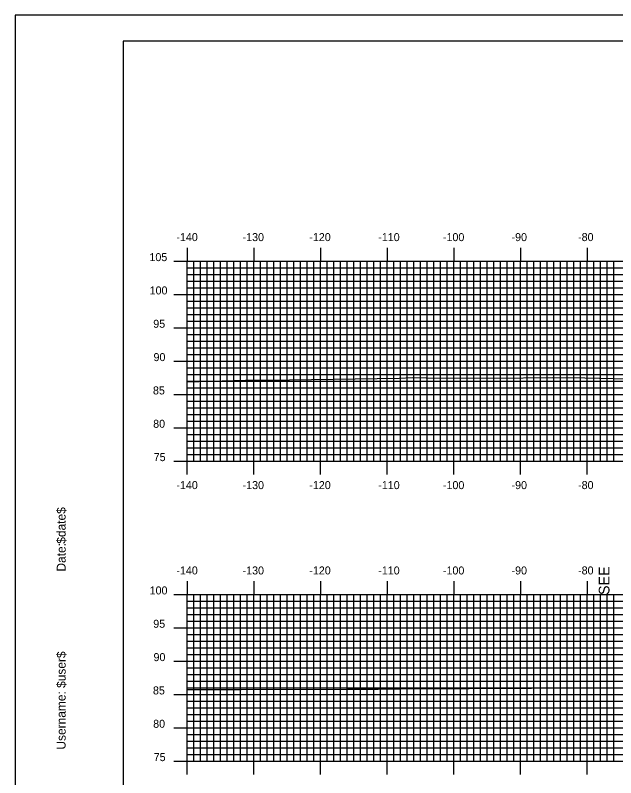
# Model space of a CAD drawing. Extents: x 854116 to 854460, y 364366 to 364586.
# Drawn here: x 854116.4 to 854206.5, y 364471.3 to 364585.7 of the extents above; entities that cross this region are included whole.
import ezdxf

# ---------------------------------------------------------------- set-up
doc = ezdxf.new("R2010")
doc.units = 0
for name, color, linetype in [('ANNOTATION', 7, 'Continuous'), ('BORDER', 7, 'Continuous'), ('H_V ANNOTATION', 7, 'Continuous'), ('MAJOR', 7, 'Continuous'), ('MINOR', 7, 'Continuous'), ('PLOT BOUNDARY', 7, 'Continuous'), ('S_Roadway_Centerline', 7, 'Continuous')]:
    doc.layers.add(name, color=color, linetype=linetype)

msp = doc.modelspace()

# ---------------------------------------------------------------- linework, layer by layer
at = {"layer": 'BORDER'}
msp.add_lwpolyline([(854132.63, 364371.79), (854452.63, 364371.79), (854452.63, 364581.79), (854132.63, 364581.79)], close=True, dxfattribs=at)
at = {"layer": 'MAJOR'}
for p, q in [((854142.23, 364550.79), (854142.23, 364548.79)), ((854152.23, 364550.79), (854152.23, 364548.79)), ((854162.23, 364550.79), (854162.23, 364548.79)), ((854172.23, 364550.79), (854172.23, 364548.79)), ((854182.23, 364550.79), (854182.23, 364548.79)), ((854192.23, 364550.79), (854192.23, 364548.79)), ((854202.23, 364550.79), (854202.23, 364548.79)), ((854140.23, 364548.79), (854142.23, 364548.79)), ((854142.23, 364548.79), (854422.23, 364548.79)), ((854142.23, 364518.79), (854142.23, 364548.79)), ((854142.23, 364518.79), (854142.23, 364548.79)), ((854142.23, 364548.79), (854422.23, 364548.79)), ((854152.23, 364518.79), (854152.23, 364548.79)), ((854162.23, 364518.79), (854162.23, 364548.79)), ((854172.23, 364518.79), (854172.23, 364548.79)), ((854182.23, 364518.79), (854182.23, 364548.79)), ((854192.23, 364518.79), (854192.23, 364548.79)), ((854202.23, 364518.79), (854202.23, 364548.79)), ((854140.23, 364543.79), (854142.23, 364543.79)), ((854142.23, 364543.79), (854422.23, 364543.79)), ((854140.23, 364538.79), (854142.23, 364538.79)), ((854142.23, 364538.79), (854422.23, 364538.79)), ((854140.23, 364533.79), (854142.23, 364533.79)), ((854142.23, 364533.79), (854422.23, 364533.79)), ((854140.23, 364528.79), (854142.23, 364528.79)), ((854142.23, 364528.79), (854422.23, 364528.79)), ((854140.23, 364523.79), (854142.23, 364523.79)), ((854142.23, 364523.79), (854422.23, 364523.79)), ((854140.23, 364518.79), (854142.23, 364518.79)), ((854142.23, 364518.79), (854422.23, 364518.79)), ((854142.23, 364518.79), (854422.23, 364518.79)), ((854142.23, 364516.78), (854142.23, 364518.79)), ((854152.23, 364516.78), (854152.23, 364518.79)), ((854162.23, 364516.78), (854162.23, 364518.79)), ((854172.23, 364516.78), (854172.23, 364518.79)), ((854182.23, 364516.78), (854182.23, 364518.79)), ((854192.23, 364516.78), (854192.23, 364518.79)), ((854202.23, 364516.78), (854202.23, 364518.79)), ((854142.23, 364500.79), (854142.23, 364498.79)), ((854152.23, 364500.79), (854152.23, 364498.79)), ((854162.23, 364500.79), (854162.23, 364498.79)), ((854172.23, 364500.79), (854172.23, 364498.79)), ((854182.23, 364500.79), (854182.23, 364498.79)), ((854192.23, 364500.79), (854192.23, 364498.79)), ((854202.23, 364500.79), (854202.23, 364498.79)), ((854140.23, 364498.79), (854142.23, 364498.79)), ((854142.23, 364498.79), (854422.23, 364498.79)), ((854142.23, 364473.79), (854142.23, 364498.79)), ((854142.23, 364473.79), (854142.23, 364498.79)), ((854142.23, 364498.79), (854422.23, 364498.79)), ((854152.23, 364473.79), (854152.23, 364498.79)), ((854162.23, 364473.79), (854162.23, 364498.79)), ((854172.23, 364473.79), (854172.23, 364498.79)), ((854182.23, 364473.79), (854182.23, 364498.79)), ((854192.23, 364473.79), (854192.23, 364498.79)), ((854202.23, 364473.79), (854202.23, 364498.79)), ((854140.23, 364493.79), (854142.23, 364493.79)), ((854142.23, 364493.79), (854422.23, 364493.79)), ((854140.23, 364488.79), (854142.23, 364488.79)), ((854142.23, 364488.79), (854422.23, 364488.79)), ((854140.23, 364483.79), (854142.23, 364483.79)), ((854142.23, 364483.79), (854422.23, 364483.79)), ((854140.23, 364478.79), (854142.23, 364478.79)), ((854142.23, 364478.79), (854422.23, 364478.79)), ((854140.23, 364473.79), (854142.23, 364473.79)), ((854142.23, 364473.79), (854422.23, 364473.79)), ((854142.23, 364473.79), (854422.23, 364473.79)), ((854142.23, 364471.78), (854142.23, 364473.79)), ((854152.23, 364471.78), (854152.23, 364473.79)), ((854162.23, 364471.78), (854162.23, 364473.79)), ((854172.23, 364471.78), (854172.23, 364473.79)), ((854182.23, 364471.78), (854182.23, 364473.79)), ((854192.23, 364471.78), (854192.23, 364473.79)), ((854202.23, 364471.78), (854202.23, 364473.79))]:
    msp.add_line(p, q, dxfattribs=at)
at = {"layer": 'MINOR'}
for p, q in [((854143.23, 364518.79), (854143.23, 364548.79)), ((854144.23, 364518.79), (854144.23, 364548.79)), ((854145.23, 364518.79), (854145.23, 364548.79)), ((854146.23, 364518.79), (854146.23, 364548.79)), ((854147.23, 364518.79), (854147.23, 364548.79)), ((854148.23, 364518.79), (854148.23, 364548.79)), ((854149.23, 364518.79), (854149.23, 364548.79)), ((854150.23, 364518.79), (854150.23, 364548.79)), ((854151.23, 364518.79), (854151.23, 364548.79)), ((854153.23, 364518.79), (854153.23, 364548.79)), ((854154.23, 364518.79), (854154.23, 364548.79)), ((854155.23, 364518.79), (854155.23, 364548.79)), ((854156.23, 364518.79), (854156.23, 364548.79)), ((854157.23, 364518.79), (854157.23, 364548.79)), ((854158.23, 364518.79), (854158.23, 364548.79)), ((854159.23, 364518.79), (854159.23, 364548.79)), ((854160.23, 364518.79), (854160.23, 364548.79)), ((854161.23, 364518.79), (854161.23, 364548.79)), ((854163.23, 364518.79), (854163.23, 364548.79)), ((854164.23, 364518.79), (854164.23, 364548.79)), ((854165.23, 364518.79), (854165.23, 364548.79)), ((854166.23, 364518.79), (854166.23, 364548.79)), ((854167.23, 364518.79), (854167.23, 364548.79)), ((854168.23, 364518.79), (854168.23, 364548.79)), ((854169.23, 364518.79), (854169.23, 364548.79)), ((854170.23, 364518.79), (854170.23, 364548.79)), ((854171.23, 364518.79), (854171.23, 364548.79)), ((854173.23, 364518.79), (854173.23, 364548.79)), ((854174.23, 364518.79), (854174.23, 364548.79)), ((854175.23, 364518.79), (854175.23, 364548.79)), ((854176.23, 364518.79), (854176.23, 364548.79)), ((854177.23, 364518.79), (854177.23, 364548.79)), ((854178.23, 364518.79), (854178.23, 364548.79)), ((854179.23, 364518.79), (854179.23, 364548.79)), ((854180.23, 364518.79), (854180.23, 364548.79)), ((854181.23, 364518.79), (854181.23, 364548.79)), ((854183.23, 364518.79), (854183.23, 364548.79)), ((854184.23, 364518.79), (854184.23, 364548.79)), ((854185.23, 364518.79), (854185.23, 364548.79)), ((854186.23, 364518.79), (854186.23, 364548.79)), ((854187.23, 364518.79), (854187.23, 364548.79)), ((854188.23, 364518.79), (854188.23, 364548.79)), ((854189.23, 364518.79), (854189.23, 364548.79)), ((854190.23, 364518.79), (854190.23, 364548.79)), ((854191.23, 364518.79), (854191.23, 364548.79)), ((854193.23, 364518.79), (854193.23, 364548.79)), ((854194.23, 364518.79), (854194.23, 364548.79)), ((854195.23, 364518.79), (854195.23, 364548.79)), ((854196.23, 364518.79), (854196.23, 364548.79)), ((854197.23, 364518.79), (854197.23, 364548.79)), ((854198.23, 364518.79), (854198.23, 364548.79)), ((854199.23, 364518.79), (854199.23, 364548.79)), ((854200.23, 364518.79), (854200.23, 364548.79)), ((854201.23, 364518.79), (854201.23, 364548.79)), ((854203.23, 364518.79), (854203.23, 364548.79)), ((854204.23, 364518.79), (854204.23, 364548.79)), ((854205.23, 364518.79), (854205.23, 364548.79)), ((854206.23, 364518.79), (854206.23, 364548.79)), ((854142.23, 364547.79), (854422.23, 364547.79)), ((854142.23, 364547.79), (854144.23, 364547.79)), ((854142.23, 364546.79), (854422.23, 364546.79)), ((854142.23, 364546.79), (854144.23, 364546.79)), ((854142.23, 364545.79), (854422.23, 364545.79)), ((854142.23, 364545.79), (854144.23, 364545.79)), ((854142.23, 364544.79), (854422.23, 364544.79)), ((854142.23, 364544.79), (854144.23, 364544.79)), ((854142.23, 364542.79), (854422.23, 364542.79)), ((854142.23, 364542.79), (854144.23, 364542.79)), ((854142.23, 364541.79), (854422.23, 364541.79)), ((854142.23, 364541.79), (854144.23, 364541.79)), ((854142.23, 364540.79), (854422.23, 364540.79)), ((854142.23, 364540.79), (854144.23, 364540.79)), ((854142.23, 364539.79), (854422.23, 364539.79)), ((854142.23, 364539.79), (854144.23, 364539.79)), ((854142.23, 364537.79), (854422.23, 364537.79)), ((854142.23, 364537.79), (854144.23, 364537.79)), ((854142.23, 364536.79), (854422.23, 364536.79)), ((854142.23, 364536.79), (854144.23, 364536.79)), ((854142.23, 364535.79), (854422.23, 364535.79)), ((854142.23, 364535.79), (854144.23, 364535.79)), ((854142.23, 364534.79), (854422.23, 364534.79)), ((854142.23, 364534.79), (854144.23, 364534.79)), ((854142.23, 364532.79), (854422.23, 364532.79)), ((854142.23, 364532.79), (854144.23, 364532.79)), ((854142.23, 364531.79), (854422.23, 364531.79)), ((854142.23, 364531.79), (854144.23, 364531.79)), ((854142.23, 364530.79), (854422.23, 364530.79)), ((854142.23, 364530.79), (854144.23, 364530.79)), ((854142.23, 364529.79), (854422.23, 364529.79)), ((854142.23, 364529.79), (854144.23, 364529.79)), ((854142.23, 364527.79), (854422.23, 364527.79)), ((854142.23, 364527.79), (854144.23, 364527.79)), ((854142.23, 364526.79), (854422.23, 364526.79)), ((854142.23, 364526.79), (854144.23, 364526.79)), ((854142.23, 364525.79), (854422.23, 364525.79)), ((854142.23, 364525.79), (854144.23, 364525.79)), ((854142.23, 364524.79), (854422.23, 364524.79)), ((854142.23, 364524.79), (854144.23, 364524.79)), ((854142.23, 364522.79), (854422.23, 364522.79)), ((854142.23, 364522.79), (854144.23, 364522.79)), ((854142.23, 364521.79), (854422.23, 364521.79)), ((854142.23, 364521.79), (854144.23, 364521.79)), ((854142.23, 364520.79), (854422.23, 364520.79)), ((854142.23, 364520.79), (854144.23, 364520.79)), ((854142.23, 364519.79), (854422.23, 364519.79)), ((854142.23, 364519.79), (854144.23, 364519.79)), ((854143.23, 364473.79), (854143.23, 364498.79)), ((854144.23, 364473.79), (854144.23, 364498.79)), ((854145.23, 364473.79), (854145.23, 364498.79)), ((854146.23, 364473.79), (854146.23, 364498.79)), ((854147.23, 364473.79), (854147.23, 364498.79)), ((854148.23, 364473.79), (854148.23, 364498.79)), ((854149.23, 364473.79), (854149.23, 364498.79)), ((854150.23, 364473.79), (854150.23, 364498.79)), ((854151.23, 364473.79), (854151.23, 364498.79)), ((854153.23, 364473.79), (854153.23, 364498.79)), ((854154.23, 364473.79), (854154.23, 364498.79)), ((854155.23, 364473.79), (854155.23, 364498.79)), ((854156.23, 364473.79), (854156.23, 364498.79)), ((854157.23, 364473.79), (854157.23, 364498.79)), ((854158.23, 364473.79), (854158.23, 364498.79)), ((854159.23, 364473.79), (854159.23, 364498.79)), ((854160.23, 364473.79), (854160.23, 364498.79)), ((854161.23, 364473.79), (854161.23, 364498.79)), ((854163.23, 364473.79), (854163.23, 364498.79)), ((854164.23, 364473.79), (854164.23, 364498.79)), ((854165.23, 364473.79), (854165.23, 364498.79)), ((854166.23, 364473.79), (854166.23, 364498.79)), ((854167.23, 364473.79), (854167.23, 364498.79)), ((854168.23, 364473.79), (854168.23, 364498.79)), ((854169.23, 364473.79), (854169.23, 364498.79)), ((854170.23, 364473.79), (854170.23, 364498.79)), ((854171.23, 364473.79), (854171.23, 364498.79)), ((854173.23, 364473.79), (854173.23, 364498.79)), ((854174.23, 364473.79), (854174.23, 364498.79)), ((854175.23, 364473.79), (854175.23, 364498.79)), ((854176.23, 364473.79), (854176.23, 364498.79)), ((854177.23, 364473.79), (854177.23, 364498.79)), ((854178.23, 364473.79), (854178.23, 364498.79)), ((854179.23, 364473.79), (854179.23, 364498.79)), ((854180.23, 364473.79), (854180.23, 364498.79)), ((854181.23, 364473.79), (854181.23, 364498.79)), ((854183.23, 364473.79), (854183.23, 364498.79)), ((854184.23, 364473.79), (854184.23, 364498.79)), ((854185.23, 364473.79), (854185.23, 364498.79)), ((854186.23, 364473.79), (854186.23, 364498.79)), ((854187.23, 364473.79), (854187.23, 364498.79)), ((854188.23, 364473.79), (854188.23, 364498.79)), ((854189.23, 364473.79), (854189.23, 364498.79)), ((854190.23, 364473.79), (854190.23, 364498.79)), ((854191.23, 364473.79), (854191.23, 364498.79)), ((854193.23, 364473.79), (854193.23, 364498.79)), ((854194.23, 364473.79), (854194.23, 364498.79)), ((854195.23, 364473.79), (854195.23, 364498.79)), ((854196.23, 364473.79), (854196.23, 364498.79)), ((854197.23, 364473.79), (854197.23, 364498.79)), ((854198.23, 364473.79), (854198.23, 364498.79)), ((854199.23, 364473.79), (854199.23, 364498.79)), ((854200.23, 364473.79), (854200.23, 364498.79)), ((854201.23, 364473.79), (854201.23, 364498.79)), ((854203.23, 364473.79), (854203.23, 364498.79)), ((854204.23, 364473.79), (854204.23, 364498.79)), ((854205.23, 364473.79), (854205.23, 364498.79)), ((854206.23, 364473.79), (854206.23, 364498.79)), ((854142.23, 364497.79), (854422.23, 364497.79)), ((854142.23, 364497.79), (854144.23, 364497.79)), ((854142.23, 364496.79), (854422.23, 364496.79)), ((854142.23, 364496.79), (854144.23, 364496.79)), ((854142.23, 364495.79), (854422.23, 364495.79)), ((854142.23, 364495.79), (854144.23, 364495.79)), ((854142.23, 364494.79), (854422.23, 364494.79)), ((854142.23, 364494.79), (854144.23, 364494.79)), ((854142.23, 364492.79), (854422.23, 364492.79)), ((854142.23, 364492.79), (854144.23, 364492.79)), ((854142.23, 364491.79), (854422.23, 364491.79)), ((854142.23, 364491.79), (854144.23, 364491.79)), ((854142.23, 364490.79), (854422.23, 364490.79)), ((854142.23, 364490.79), (854144.23, 364490.79)), ((854142.23, 364489.79), (854422.23, 364489.79)), ((854142.23, 364489.79), (854144.23, 364489.79)), ((854142.23, 364487.79), (854422.23, 364487.79)), ((854142.23, 364487.79), (854144.23, 364487.79)), ((854142.23, 364486.79), (854422.23, 364486.79)), ((854142.23, 364486.79), (854144.23, 364486.79)), ((854142.23, 364485.79), (854422.23, 364485.79)), ((854142.23, 364485.79), (854144.23, 364485.79)), ((854142.23, 364484.79), (854422.23, 364484.79)), ((854142.23, 364484.79), (854144.23, 364484.79)), ((854142.23, 364482.79), (854422.23, 364482.79)), ((854142.23, 364482.79), (854144.23, 364482.79)), ((854142.23, 364481.79), (854422.23, 364481.79)), ((854142.23, 364481.79), (854144.23, 364481.79)), ((854142.23, 364480.79), (854422.23, 364480.79)), ((854142.23, 364480.79), (854144.23, 364480.79)), ((854142.23, 364479.79), (854422.23, 364479.79)), ((854142.23, 364479.79), (854144.23, 364479.79)), ((854142.23, 364477.79), (854422.23, 364477.79)), ((854142.23, 364477.79), (854144.23, 364477.79)), ((854142.23, 364476.79), (854422.23, 364476.79)), ((854142.23, 364476.79), (854144.23, 364476.79)), ((854142.23, 364475.79), (854422.23, 364475.79)), ((854142.23, 364475.79), (854144.23, 364475.79)), ((854142.23, 364474.79), (854422.23, 364474.79)), ((854142.23, 364474.79), (854144.23, 364474.79))]:
    msp.add_line(p, q, dxfattribs=at)
at = {"layer": 'PLOT BOUNDARY'}
msp.add_lwpolyline([(854116.44, 364365.67), (854456.44, 364365.67), (854456.44, 364585.67), (854116.44, 364585.67)], close=True, dxfattribs=at)
at = {"layer": 'S_Roadway_Centerline'}
for points in [[(854142.23, 364530.7), (854150.96, 364530.91), (854154.29, 364530.94), (854174.01, 364531.22), (854175.96, 364531.33), (854178.09, 364531.3), (854188.23, 364531.21), (854197.05, 364531.33), (854201.89, 364531.3), (854210.62, 364531.08)], [(854142.23, 364484.51), (854145.43, 364484.53), (854150.31, 364484.55), (854166.25, 364484.59), (854170.89, 364484.6), (854177.65, 364484.66), (854184.53, 364484.68), (854193.85, 364484.73), (854205.16, 364484.77), (854206.43, 364484.76), (854208.95, 364484.74), (854225.49, 364484.59), (854233.76, 364484.6), (854246.53, 364484.54), (854262.03, 364484.59), (854265.28, 364484.63), (854275.82, 364484.44), (854286.51, 364484.21), (854289.54, 364484.19), (854299.47, 364484.14), (854307.05, 364483.9), (854318.1, 364483.75), (854326.02, 364483.77)]]:
    msp.add_lwpolyline(points, dxfattribs=at)

# ---------------------------------------------------------------- texts
at = {"layer": 'ANNOTATION'}
msp.add_text('SEE', height=1.6, rotation=90, dxfattribs=at).set_placement((854205.57, 364498.71))
at = {"layer": 'BORDER'}
for s, p in [('$date$', (854124, 364506.4)), ('Date:', (854124, 364502.22)), ('$user$', (854124, 364484.77)), ('Username:', (854124, 364475.52))]:
    msp.add_text(s, height=1.339, rotation=90, dxfattribs=at).set_placement(p)
at = {"layer": 'H_V ANNOTATION'}
for s, p in [('-140', (854140.61, 364551.79)), ('-130', (854150.54, 364551.79)), ('-120', (854160.55, 364551.79)), ('-110', (854170.89, 364551.79)), ('-100', (854180.59, 364551.79)), ('-90', (854190.88, 364551.79)), ('-80', (854200.86, 364551.79)), ('105', (854136.57, 364548.79)), ('100', (854136.6, 364543.79)), ('95', (854137.14, 364538.79)), ('90', (854137.18, 364533.79)), ('85', (854137.1, 364528.79)), ('80', (854137.13, 364523.79)), ('75', (854137.21, 364518.79)), ('-140', (854140.61, 364514.59)), ('-130', (854150.54, 364514.59)), ('-120', (854160.55, 364514.59)), ('-110', (854170.89, 364514.59)), ('-100', (854180.59, 364514.59)), ('-90', (854190.88, 364514.59)), ('-80', (854200.86, 364514.59)), ('-140', (854140.61, 364501.79)), ('-130', (854150.54, 364501.79)), ('-120', (854160.55, 364501.79)), ('-110', (854170.89, 364501.79)), ('-100', (854180.59, 364501.79)), ('-90', (854190.88, 364501.79)), ('-80', (854200.86, 364501.79)), ('100', (854136.6, 364498.79)), ('95', (854137.14, 364493.79)), ('90', (854137.18, 364488.79)), ('85', (854137.1, 364483.79)), ('80', (854137.13, 364478.79)), ('75', (854137.21, 364473.79))]:
    msp.add_text(s, height=1.2, dxfattribs=at).set_placement(p)
at = {"layer": 'MAJOR'}
for p in [(854142.22, 364518.79), (854142.22, 364473.79)]:
    msp.add_text('-', height=0.012, dxfattribs=at).set_placement(p)

doc.saveas('drawing.dxf')
